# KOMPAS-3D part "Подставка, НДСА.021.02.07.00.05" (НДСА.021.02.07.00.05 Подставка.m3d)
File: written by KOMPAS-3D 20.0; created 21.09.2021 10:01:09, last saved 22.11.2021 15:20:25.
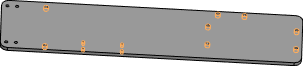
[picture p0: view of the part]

Document properties: Полное имя файла: C:\Users\korychko\Desktop\PLM\НДСА.021.02.07.00.05 Подставка.m3d

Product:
- Part/product: Подставка  | designation НДСА.021.02.07.00.05
    Материал: АМг6  ГОСТ 4784-2019 (density 2640 kg/m3)
    Масса: 1.88583
    additional columns: <item xmlns="http://appius.ru/pdm" xmlns:xs="http://www.w3.org/2001/XMLSchema" x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; <item xmlns="http://appius.ru/pdm" xmlns:xs="http://www.w3.org/2001/XMLSchema" x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; <item xmlns="http://appius.ru/pdm" xmlns:xs="http://www.w3.org/2001/XMLSchema" x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; <item xmlns="http://appius.ru/pdm" xmlns:xs="http://www.w3.org/2001/XMLSchema" x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; <item xmlns="http://appius.ru/pdm" xmlns:xs="http://www.w3.org/2001/XMLSchema" x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; <item xmlns="http://appius.ru/pdm" xmlns:xs="http://www.w3.org/2001/XMLSchema" x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; <item xmlns="http://appius.ru/pdm" xmlns:xs="http://www.w3.org/2001/XMLSchema" x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; <item xmlns="http://appius.ru/pdm" xmlns:xs="http://www.w3.org/2001/XMLSchema" x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
    source file: НДСА.021.02.07.00.05 Подставка.cdw

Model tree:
1. Эскиз:1
2. Элемент выдавливания:1
     Расстояние 1 = 8
3. Эскиз:2  (with: Элемент выдавливания:1)
4. Элемент выдавливания:2
     Расстояние 2 = 8
5. Фаска:1  (with: Элемент выдавливания:2)
     Угол = 45; Длина 1 = 2.8; Длина 2 = 2.8
6. Скругление:1  (with: Элемент выдавливания:1)
     Радиус = 15
7. Эскиз:3  (with: Элемент выдавливания:1)
8. Отверстие:1  (with: Элемент выдавливания:1)  (labels: M10)
     Глубина выреза = 8; Диаметр отверстия = 8.3762; Угол конуса дна = 118; Расстояние 1 = 6.6; Расстояние 2 = 501.5
9. M10  (with: Элемент выдавливания:1)  (labels: M10; cil0_24705-2004 coarse)
     Длина резьбы = 8; Шаг резьбы = 1.5; Номинальный диаметр резьбы = 10
10. Отверстие:2  (with: Элемент выдавливания:1, M10)  (labels: M10; cil0_24705-2004 coarse)
     Глубина выреза = 8; Диаметр отверстия = 8.3762; Угол конуса дна = 118; Расстояние 1 = 6.6; Расстояние 2 = 446.5; Длина резьбы = 8; Шаг резьбы = 1.5; Номинальный диаметр резьбы = 10
11. Эскиз:4  (with: Элемент выдавливания:1)
12. Отверстие:3  (with: Элемент выдавливания:1, M10)  (labels: M10; cil0_24705-2004 coarse)
     Глубина выреза = 8; Диаметр отверстия = 8.3762; Угол конуса дна = 118; Расстояние 1 = 100; Расстояние 2 = 610; Длина резьбы = 8; Шаг резьбы = 1.5; Номинальный диаметр резьбы = 10
13. Отверстие:4  (with: Элемент выдавливания:1, M10)  (labels: M10; cil0_24705-2004 coarse)
     Глубина выреза = 8; Диаметр отверстия = 8.3762; Угол конуса дна = 118; Расстояние 1 = 45; Расстояние 2 = 610; Длина резьбы = 8; Шаг резьбы = 1.5; Номинальный диаметр резьбы = 10
14. Отверстие:5  (with: Элемент выдавливания:1, M10)  (labels: M10; cil0_24705-2004 coarse)
     Глубина выреза = 8; Диаметр отверстия = 8.3762; Угол конуса дна = 118; Расстояние 1 = 100; Расстояние 2 = 427; Длина резьбы = 8; Шаг резьбы = 1.5; Номинальный диаметр резьбы = 10
15. Отверстие:6  (with: Элемент выдавливания:1, M10)  (labels: M10; cil0_24705-2004 coarse)
     Глубина выреза = 8; Диаметр отверстия = 8.3762; Угол конуса дна = 118; Расстояние 1 = 45; Расстояние 2 = 427; Длина резьбы = 8; Шаг резьбы = 1.5; Номинальный диаметр резьбы = 10
16. Отверстие:7  (with: Элемент выдавливания:1, M10)  (labels: M10; cil0_24705-2004 coarse)
     Глубина выреза = 8; Диаметр отверстия = 8.3762; Угол конуса дна = 118; Расстояние 1 = 132; Расстояние 2 = 92; Длина резьбы = 8; Шаг резьбы = 1.5; Номинальный диаметр резьбы = 10
17. Отверстие:8  (with: Элемент выдавливания:1, M10)  (labels: M10; cil0_24705-2004 coarse)
     Глубина выреза = 8; Диаметр отверстия = 8.3762; Угол конуса дна = 118; Расстояние 1 = 14; Расстояние 2 = 92; Длина резьбы = 8; Шаг резьбы = 1.5; Номинальный диаметр резьбы = 10
18. Эскиз:5  (with: Элемент выдавливания:1)
19. Отверстие:9  (with: Элемент выдавливания:1)  (labels: M6)
     Глубина выреза = 8; Диаметр отверстия = 4.91747; Угол конуса дна = 118; Расстояние 1 = 135; Расстояние 2 = 251
20. M6  (with: Элемент выдавливания:1)  (labels: M6; cil0_24705-2004 coarse)
     Длина резьбы = 8; Шаг резьбы = 1; Номинальный диаметр резьбы = 6
21. Отверстие:11  (with: Элемент выдавливания:1, M6)  (labels: M6; cil0_24705-2004 coarse)
     Глубина выреза = 8; Диаметр отверстия = 4.91747; Угол конуса дна = 118; Расстояние 1 = 115; Расстояние 2 = 251; Длина резьбы = 8; Шаг резьбы = 1; Номинальный диаметр резьбы = 6
22. Отверстие:13  (with: Элемент выдавливания:1, M6)  (labels: M6; cil0_24705-2004 coarse)
     Глубина выреза = 8; Диаметр отверстия = 4.91747; Угол конуса дна = 118; Расстояние 1 = 115; Расстояние 2 = 171; Длина резьбы = 8; Шаг резьбы = 1; Номинальный диаметр резьбы = 6
23. Отверстие:14  (with: Элемент выдавливания:1, M6)  (labels: M6; cil0_24705-2004 coarse; АМг6  ГОСТ 4784-2019)
     Глубина выреза = 8; Диаметр отверстия = 4.91747; Угол конуса дна = 118; Расстояние 1 = 135; Расстояние 2 = 171; Длина резьбы = 8; Шаг резьбы = 1; Номинальный диаметр резьбы = 6

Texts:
  НДСА.021.02.07.00.05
